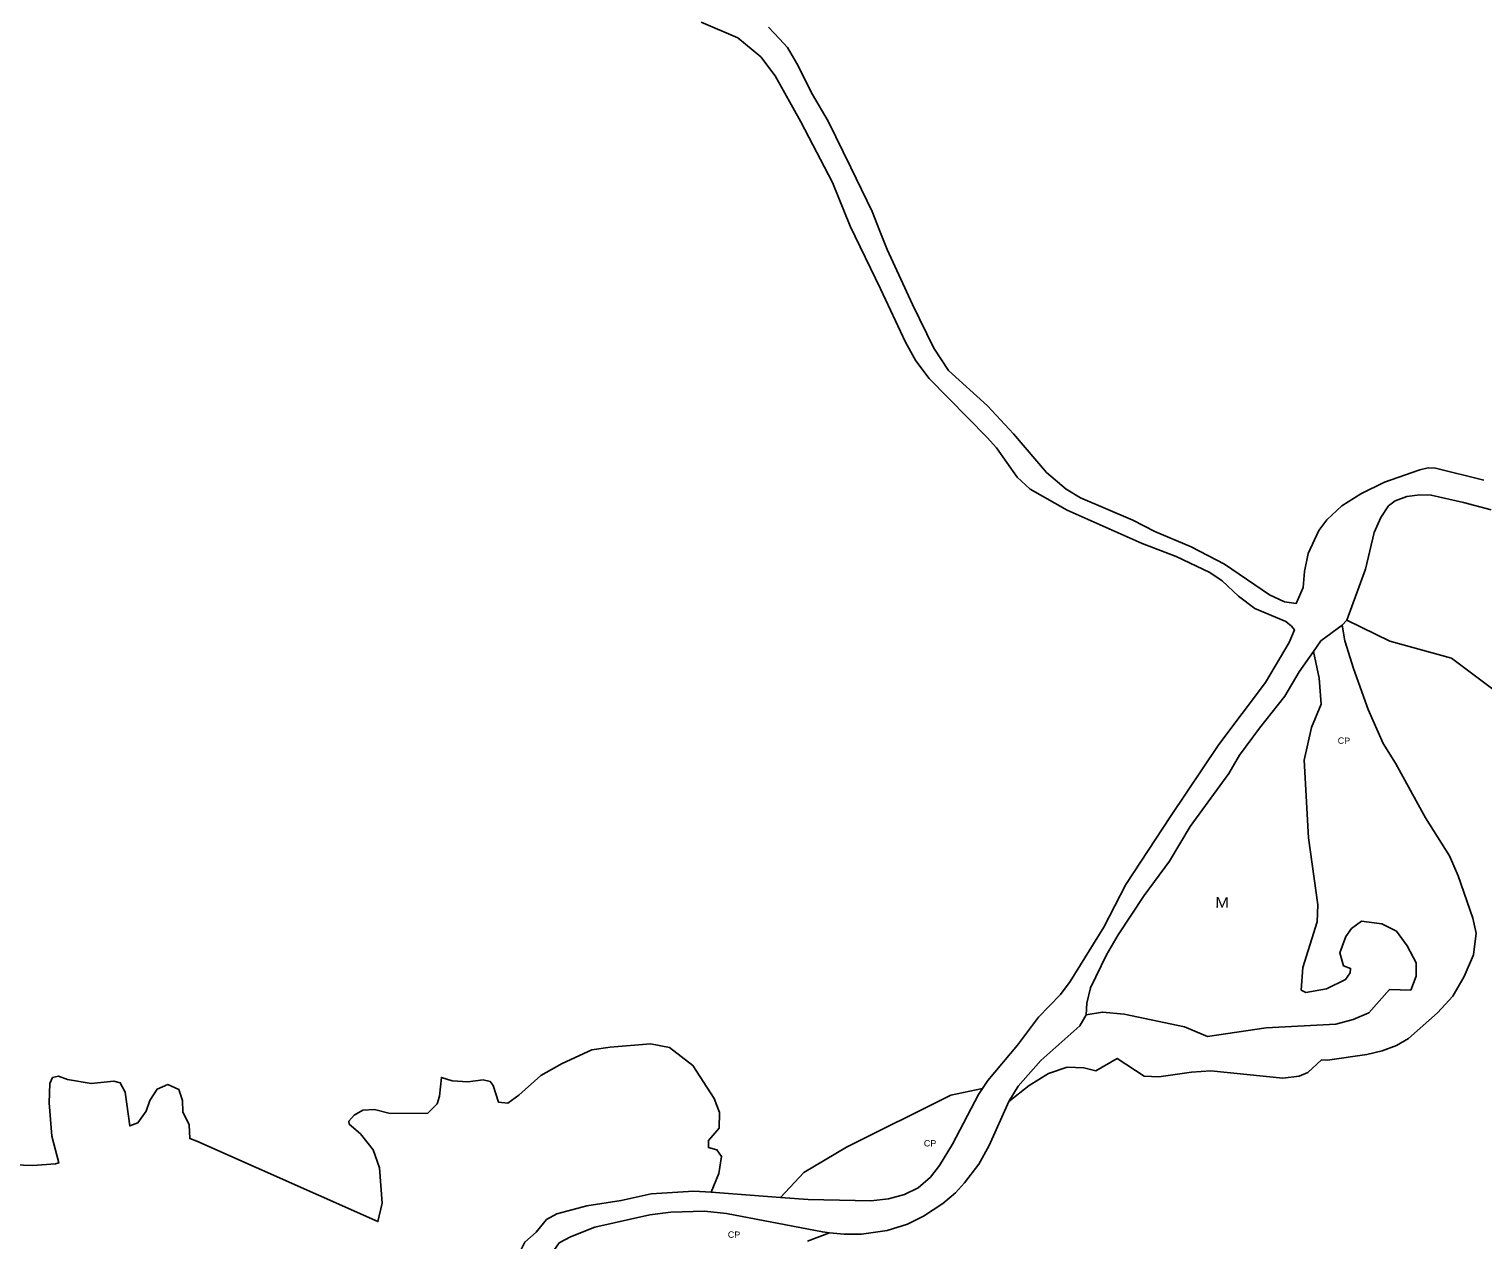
# Model space of a CAD drawing. Extents: x 713589 to 726391, y 7177764 to 7191819.
# Drawn here: x 723375 to 724832, y 7179361 to 7180574 of the extents above; entities that cross this region are included whole.
import ezdxf
from ezdxf.enums import TextEntityAlignment as Align

# ---------------------------------------------------------------- set-up
doc = ezdxf.new("R2010")
doc.units = 0
doc.header["$LTSCALE"] = 2.6
doc.layers.add('63', color=7, linetype='Continuous', lineweight=25)

msp = doc.modelspace()

# ---------------------------------------------------------------- linework, layer by layer
at = {"layer": '63'}
for p, q in [((724690.79, 7179976.99), (724695.57, 7179982.13)), ((724128.24, 7179403.97), (724058.88, 7179409.06))]:
    msp.add_line(p, q, dxfattribs=at)
for points in [[(724048.63, 7180581.22), (724085.51, 7180565.56), (724108.35, 7180546.54), (724122.78, 7180527.2), (724148.57, 7180481.24), (724180.24, 7180420.44), (724197.81, 7180376.63), (724228.47, 7180313.84), (724253.44, 7180260.55), (724263.9, 7180241.91), (724277.18, 7180224.15), (724335.06, 7180165.21), (724344.53, 7180154.87), (724365.32, 7180125.26), (724378.34, 7180113.22), (724415.3, 7180092.2), (724490.54, 7180058.98), (724524.49, 7180045.85), (724558.33, 7180029.76), (724570.73, 7180021.47), (724587.05, 7180006.18), (724603.27, 7179993.77), (724634.26, 7179980.74), (724640.01, 7179976.27), (724643.02, 7179972.47), (724637.6, 7179959.91), (724613.85, 7179919.63), (724567.24, 7179857.58), (724518.71, 7179785.32), (724474.12, 7179717.45), (724451.93, 7179674.61), (724418.42, 7179620.09), (724408.59, 7179607.07), (724386.56, 7179584.33), (724365.57, 7179556.4), (724335.82, 7179521.13), (724330.55, 7179513.05)], [(724832.61, 7180122.48), (724784.44, 7180134.26), (724777.04, 7180134.74), (724768.62, 7180132.67), (724760.83, 7180129.94), (724733.26, 7180120.29), (724709.48, 7180108.8), (724690.38, 7180096.58), (724675.28, 7180082.79), (724667.37, 7180071.85), (724656.79, 7180048.92), (724653.14, 7180030.92), (724651.62, 7180014.97), (724644.77, 7179998.94), (724633.06, 7180000.41), (724617.99, 7180007.65), (724573.05, 7180038.36), (724539.48, 7180055.55), (724503.03, 7180070.81), (724481.28, 7180082.4), (724428.77, 7180104.8), (724414.29, 7180113.2), (724394.8, 7180130.08), (724361.5, 7180168.73), (724335.57, 7180196.8), (724296.33, 7180232.3), (724281.68, 7180254.43), (724260.55, 7180298.21), (724234.92, 7180353.26), (724227.7, 7180371.86), (724220.1, 7180391.42), (724198.59, 7180435.6), (724175.81, 7180481.99), (724160.21, 7180508.54), (724144.67, 7180539.62), (724135.22, 7180555.57), (724127.2, 7180564.46), (724116.24, 7180575.97)], [(724695.57, 7179982.13), (724714.33, 7180033.25), (724723, 7180070.08), (724729.5, 7180084.93), (724737.38, 7180096.57), (724743.83, 7180101.76), (724755.49, 7180105.96), (724768.46, 7180107.64), (724779.99, 7180107.42), (724812.34, 7180100.12), (724840.08, 7180092.5)], [(724891.5, 7179875.52), (724800.41, 7179943.91), (724738.44, 7179961.08), (724695.57, 7179982.13)], [(724356.8, 7179500.16), (724377.34, 7179516.12), (724396.52, 7179527.89), (724415.42, 7179534.46), (724432.12, 7179533.63), (724444.18, 7179530.89), (724465.27, 7179543.21), (724492.38, 7179525.4), (724507.17, 7179524.85), (724540.04, 7179529.5), (724559.21, 7179530.59), (724631.25, 7179523.46), (724647.68, 7179525.37), (724656.45, 7179529.2), (724670.16, 7179541.6), (724676.18, 7179541.55), (724715.43, 7179547.08), (724730.99, 7179550.6), (724745.13, 7179556), (724757.35, 7179563.03), (724786.3, 7179588.88), (724801.51, 7179605.54), (724812.94, 7179625.35), (724822.45, 7179647), (724825.03, 7179668.7), (724821.79, 7179683.53), (724806.94, 7179725.98), (724798.24, 7179746.11), (724774.15, 7179784.14), (724744.36, 7179838.87), (724732.01, 7179858.44), (724716.81, 7179892.63), (724702.1, 7179933.88), (724693.64, 7179961.58), (724690.79, 7179976.99)], [(724662.11, 7179950.8), (724669.56, 7179961.55), (724690.79, 7179976.99)], [(724662.11, 7179950.8), (724667.76, 7179924.17), (724669.67, 7179898.14), (724660.08, 7179874.59), (724652.68, 7179842), (724657.05, 7179763.94), (724666.34, 7179697.1), (724665.79, 7179679.85), (724651.54, 7179634.38), (724649.89, 7179611.65), (724654.27, 7179609.18), (724675.09, 7179612.74), (724694.27, 7179622.32), (724698.92, 7179628.89), (724699.2, 7179633.28), (724692.08, 7179636.02), (724688.52, 7179648.89), (724694.55, 7179665.32), (724700.03, 7179673.27), (724710.17, 7179680.66), (724730.43, 7179677.92), (724745.22, 7179670.52), (724755.9, 7179656), (724764.94, 7179638.74), (724764.93, 7179625.59), (724759.45, 7179611.63), (724738.09, 7179612.18), (724717.54, 7179588.9), (724701.93, 7179582.06), (724684.4, 7179577.4), (724614.55, 7179573.86), (724555.96, 7179565.1), (724532.83, 7179574.76), (724472.33, 7179587.32), (724450.58, 7179589.59), (724434.53, 7179586.86)], [(724434.53, 7179586.86), (724434.89, 7179598.45), (724438.86, 7179613.76), (724454.76, 7179646.89), (724466.35, 7179667.04), (724492.51, 7179706.39), (724517.73, 7179740.63), (724538.46, 7179775.45), (724577.32, 7179828.7), (724588, 7179846.88), (724607.89, 7179874.04), (724633.3, 7179906.07), (724647.88, 7179930.27), (724662.11, 7179950.8)], [(724356.8, 7179500.16), (724366.17, 7179515.47), (724389, 7179541.08), (724428.07, 7179575.77), (724434.53, 7179586.86)], [(724058.88, 7179409.06), (724066.29, 7179427.9), (724068.95, 7179445), (724064.53, 7179451.48), (724055.98, 7179453.85), (724055.98, 7179460.92), (724066.6, 7179473.3), (724067.19, 7179488.93), (724061.89, 7179503.08), (724040.37, 7179536.11), (724017.08, 7179554.1), (723997.92, 7179557.64), (723957.52, 7179554.41), (723939.24, 7179551.76), (723909.46, 7179538.2), (723888.23, 7179526.12), (723866.11, 7179506.37), (723854.91, 7179498.41), (723845.77, 7179499.3), (723840.46, 7179516.1), (723837.52, 7179519.94), (723830.44, 7179521.71), (723815.11, 7179519.65), (723799.19, 7179520.83), (723788.57, 7179524.08), (723786.51, 7179505.5), (723784.14, 7179497.54), (723775, 7179488.4), (723737.26, 7179488.12), (723721.34, 7179491.95), (723709.84, 7179491.36), (723701.29, 7179486.35), (723695.69, 7179480.16), (723696.28, 7179477.22), (723707.48, 7179467.48), (723720.15, 7179451.56), (723726.64, 7179433.57), (723729.28, 7179398.19), (723724.94, 7179379.71), (723543.39, 7179460.43), (723536.4, 7179462.8), (723535.82, 7179476.68), (723529.63, 7179489.66), (723529.04, 7179500.86), (723525.51, 7179512.07), (723514.6, 7179517.08), (723503.69, 7179512.36), (723496.61, 7179500.87), (723492.77, 7179490.25), (723484.52, 7179478.76), (723476.26, 7179475.52), (723471.84, 7179509.42), (723466.83, 7179518.56), (723460.35, 7179520.33), (723437.64, 7179517.98), (723414.06, 7179522.11), (723404.92, 7179525.36), (723399.02, 7179523.89), (723396.37, 7179517.99), (723395.48, 7179498.83), (723398.42, 7179465.21), (723405.39, 7179438.47), (723401.86, 7179437.47), (723379.16, 7179436), (723284.22, 7179439.26)], [(724128.24, 7179403.97), (724151.5, 7179429.06), (724194.26, 7179454.41), (724298.65, 7179506.27), (724330.55, 7179513.05)], [(724330.55, 7179513.05), (724326.53, 7179506.89), (724300.53, 7179457.31), (724287.58, 7179435.93), (724278.53, 7179424.35), (724265.98, 7179413.62), (724252.53, 7179406.83), (724236.26, 7179402.39), (724218.61, 7179400.5), (724156.06, 7179401.93), (724128.24, 7179403.97)], [(724177.33, 7179368.62), (724191.86, 7179366.98), (724209.19, 7179367.27), (724235.16, 7179370.86), (724255.56, 7179377.16), (724271.32, 7179385.09), (724290.68, 7179397.87), (724303.52, 7179408.41), (724312.57, 7179418.5), (724326.8, 7179437.17), (724337.29, 7179455.83), (724356.8, 7179500.16)], [(724058.88, 7179409.06), (724041.46, 7179410.34), (723998.72, 7179407.66), (723968.68, 7179400.98), (723934.33, 7179395.48), (723904.13, 7179387.58), (723893.77, 7179381.72), (723883.41, 7179369.05), (723872.17, 7179359.04), (723866.66, 7179348.28), (723866.66, 7179348.03), (723866.68, 7179339.76), (723870.33, 7179326.1), (723873.68, 7179319.36), (723880.74, 7179311.16), (723916.75, 7179266.39), (723940.29, 7179251.37), (723946.73, 7179245.59), (723971.49, 7179213.68), (723982.46, 7179196.16), (724018.23, 7179146.57), (724039.37, 7179127.5), (724044.93, 7179121.58)], [(723906.36, 7179327.59), (723900.2, 7179342.41), (723900.97, 7179350.8), (723906.59, 7179358.31), (723917.89, 7179364.61), (723942.31, 7179374.3), (723997.24, 7179386.35), (724018.38, 7179389.12), (724051.91, 7179390.12), (724074.06, 7179387.8), (724170.13, 7179369.43), (724177.33, 7179368.62)], [(724155.2, 7179360.15), (724177.33, 7179368.62)]]:
    msp.add_lwpolyline(points, dxfattribs=at)

# ---------------------------------------------------------------- texts
for s, height, width, p in [('CP', 6.4, 1.05, (724692.56, 7179858.23)), ('M', 10.4, 1.2, (724570.49, 7179694.21)), ('CP', 6.4, 1.05, (724277.95, 7179454.95)), ('CP', 6.4, 1.05, (724081.58, 7179363.45))]:
    msp.add_text(s, height=height, rotation=359.062, dxfattribs=dict(at, width=width)).set_placement(p, align=Align.CENTER)

doc.saveas('drawing.dxf')
